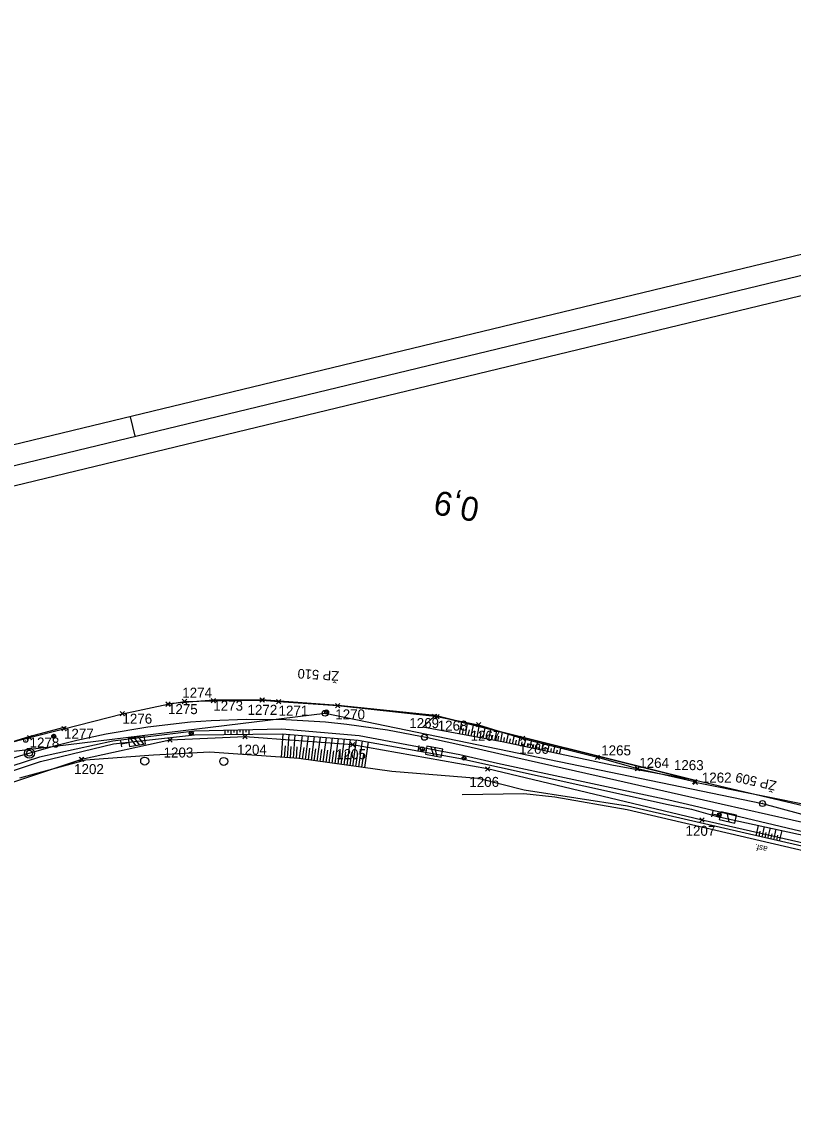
# Model space of a CAD drawing. Extents: x -738085 to -734426, y -1122197 to -1119748.
# Drawn here: x -734969.6 to -734776.9, y -1120258.1 to -1119984.4 of the extents above; entities that cross this region are included whole.
import ezdxf

# ---------------------------------------------------------------- set-up
doc = ezdxf.new("R2010")
doc.units = 0
for name, color, linetype in [('SŽDC', 7, 'Continuous'), ('Vrstva 1', 7, 'Continuous'), ('Vrstva 11', 7, 'Continuous'), ('Vrstva 12', 7, 'Continuous'), ('Vrstva 17', 7, 'Continuous'), ('Vrstva 43', 7, 'Continuous'), ('Vrstva 48', 7, 'Continuous'), ('Vrstva 49', 7, 'Continuous'), ('Vrstva 51', 7, 'Continuous'), ('Vrstva 60', 7, 'Continuous'), ('Vrstva 63', 7, 'Continuous'), ('Vrstva 7', 7, 'Continuous')]:
    doc.layers.add(name, color=color, linetype=linetype)

msp = doc.modelspace()

# ---------------------------------------------------------------- linework, layer by layer
at = {"layer": 'SŽDC'}
for p, q in [((-734933.15, -1120154.76), (-734929.02, -1120154.1)), ((-734929.02, -1120154.1), (-734921.83, -1120153.89)), ((-734921.83, -1120153.89), (-734909.61, -1120153.73)), ((-734909.61, -1120153.73), (-734905.52, -1120154.11)), ((-734905.52, -1120154.11), (-734890.73, -1120155.13)), ((-734944.53, -1120157.15), (-734933.15, -1120154.76)), ((-734890.73, -1120155.13), (-734866.49, -1120157.8)), ((-734959.14, -1120160.9), (-734944.53, -1120157.15)), ((-734866.49, -1120157.8), (-734865.95, -1120157.86)), ((-734865.95, -1120157.86), (-734855.52, -1120159.91)), ((-734967.74, -1120163.1), (-734959.14, -1120160.9)), ((-734855.52, -1120159.91), (-734844.53, -1120163.32)), ((-734977.11, -1120165.51), (-734967.74, -1120163.1)), ((-734932.65, -1120163.73), (-734954.75, -1120168.56)), ((-734913.87, -1120162.91), (-734932.65, -1120163.73)), ((-734887.03, -1120164.91), (-734913.87, -1120162.91)), ((-734853.28, -1120170.95), (-734887.03, -1120164.91)), ((-734844.53, -1120163.32), (-734825.83, -1120168.01)), ((-734954.75, -1120168.56), (-734977.62, -1120176.17)), ((-734825.83, -1120168.01), (-734815.83, -1120170.85)), ((-734799.69, -1120183.7), (-734853.28, -1120170.95)), ((-734815.83, -1120170.85), (-734801.55, -1120174.11)), ((-734801.55, -1120174.11), (-734801.4, -1120174.28)), ((-734801.4, -1120174.28), (-734758.4, -1120182.87)), ((-734748.46, -1120195.41), (-734799.69, -1120183.7))]:
    msp.add_line(p, q, dxfattribs=at)
at = {"layer": 'Vrstva 1'}
msp.add_line((-734941.35, -1120087.84), (-734942.52, -1120082.99), dxfattribs=at)
for points in [[(-734534.27, -1119984.39), (-735554.91, -1120230.88), (-735485.2, -1120519.57), (-734464.55, -1120273.08)], [(-734470.58, -1120269.4), (-735481.51, -1120513.53), (-735548.88, -1120234.56), (-734537.95, -1119990.43)], [(-734541.63, -1119996.45), (-735348.44, -1120191.3), (-735283.42, -1120460.56), (-734476.61, -1120265.71)]]:
    msp.add_lwpolyline(points, close=True, dxfattribs=at)
for points in [[(-734858.48, -1120165.34), (-734868.3, -1120163.18), (-734878.26, -1120161.29), (-734888.48, -1120159.82), (-734893.81, -1120159.28), (-734903.72, -1120158.67), (-734913.62, -1120158.56), (-734922.39, -1120158.89), (-734927.49, -1120159.26), (-734938.14, -1120160.47), (-734948.63, -1120162.22), (-734955.93, -1120163.8), (-734961.26, -1120165.13), (-734970.23, -1120167.73), (-734979.17, -1120170.78), (-734984.57, -1120172.85), (-734992.91, -1120176.44), (-734998.02, -1120178.89), (-735005.2, -1120182.65), (-735013.61, -1120187.35), (-735022.2, -1120192.38), (-735037.65, -1120201.44), (-735048.63, -1120207.9)], [(-734858.48, -1120165.34), (-734868.3, -1120163.18), (-734878.26, -1120161.29), (-734888.48, -1120159.82), (-734893.81, -1120159.28), (-734903.72, -1120158.67), (-734913.62, -1120158.56), (-734922.39, -1120158.89), (-734927.49, -1120159.26), (-734938.14, -1120160.47), (-734948.63, -1120162.22), (-734955.93, -1120163.8), (-734961.26, -1120165.13), (-734970.23, -1120167.73), (-734979.17, -1120170.78), (-734984.57, -1120172.85), (-734992.91, -1120176.44), (-734998.02, -1120178.89), (-735005.2, -1120182.65), (-735013.61, -1120187.35), (-735022.2, -1120192.38), (-735037.65, -1120201.44), (-735048.63, -1120207.9)], [(-734613.42, -1120220.79), (-734634.89, -1120215.96), (-734653.9, -1120211.66), (-734667.21, -1120208.65), (-734679.78, -1120205.8), (-734683.65, -1120204.92), (-734685.4, -1120204.52), (-734700.12, -1120201.2), (-734707.73, -1120199.48), (-734730.99, -1120194.2), (-734759.47, -1120187.75), (-734794.9, -1120179.75), (-734825.42, -1120172.84), (-734846.46, -1120168.09), (-734858.48, -1120165.34)], [(-734613.42, -1120220.79), (-734634.89, -1120215.96), (-734653.9, -1120211.66), (-734667.21, -1120208.65), (-734679.78, -1120205.8), (-734683.65, -1120204.92), (-734685.4, -1120204.52), (-734700.12, -1120201.2), (-734707.73, -1120199.48), (-734730.99, -1120194.2), (-734759.47, -1120187.75), (-734794.9, -1120179.75), (-734825.42, -1120172.84), (-734846.46, -1120168.09), (-734858.48, -1120165.34)]]:
    msp.add_lwpolyline(points, dxfattribs=at)
at = {"layer": 'Vrstva 11'}
for p, q in [((-734893.29, -1120156.29), (-734894, -1120156.87)), ((-734893.06, -1120156.58), (-734893.76, -1120157.16)), ((-734961.61, -1120162.28), (-734962.06, -1120163.09)), ((-734927.17, -1120161.59), (-734927.75, -1120162.31)), ((-734926.88, -1120161.83), (-734927.45, -1120162.54)), ((-734961.29, -1120162.47), (-734961.73, -1120163.27)), ((-734858.86, -1120167.84), (-734859.64, -1120168.33)), ((-734858.66, -1120168.16), (-734859.44, -1120168.64)), ((-734795.13, -1120182.08), (-734795.91, -1120182.57)), ((-734794.93, -1120182.4), (-734795.71, -1120182.89))]:
    msp.add_line(p, q, dxfattribs=at)
for centre in [(-734893.53, -1120156.72), (-734961.68, -1120162.78), (-734927.32, -1120162.06), (-734859.15, -1120168.24), (-734795.43, -1120182.48)]:
    msp.add_circle(centre, 0.5, dxfattribs=at)
at = {"layer": 'Vrstva 12'}
msp.add_lwpolyline([(-734795.73, -1120182), (-734794.95, -1120182.18), (-734795.12, -1120182.96), (-734795.9, -1120182.78), (-734795.73, -1120182)], dxfattribs=at)
at = {"layer": 'Vrstva 17'}
for points in [[(-734749.98, -1120183.69), (-734758.44, -1120182.92), (-734774.19, -1120180.25), (-734801.33, -1120173.81), (-734866.4, -1120157.58), (-734890.66, -1120155.06), (-734909.69, -1120153.67), (-734921.82, -1120153.78), (-734933.01, -1120154.69)], [(-734958.83, -1120160.54), (-734967.92, -1120162.89), (-734987.55, -1120168.9), (-734992.59, -1120171.25), (-735002.18, -1120175.82), (-735016.31, -1120182.77), (-735022.02, -1120185.92), (-735031.95, -1120191.31), (-735046.51, -1120198.52), (-735062.17, -1120206.65)]]:
    msp.add_lwpolyline(points, dxfattribs=at)
at = {"layer": 'Vrstva 43'}
for centre in [(-734938.97, -1120168.99), (-734919.21, -1120169.05)]:
    msp.add_circle(centre, 1, dxfattribs=at)
at = {"layer": 'Vrstva 48'}
for p, q in [((-734860.31, -1120162.2), (-734859.76, -1120159.24)), ((-734858.83, -1120162.47), (-734858.3, -1120159.6)), ((-734918.96, -1120161.37), (-734918.94, -1120162.34)), ((-734918.21, -1120161.35), (-734918.2, -1120161.84)), ((-734917.46, -1120161.33), (-734917.44, -1120162.33)), ((-734916.71, -1120161.31), (-734916.7, -1120161.82)), ((-734915.96, -1120161.3), (-734915.94, -1120162.31)), ((-734915.21, -1120161.28), (-734915.2, -1120161.79)), ((-734914.46, -1120161.26), (-734914.44, -1120162.3)), ((-734913.71, -1120161.25), (-734913.7, -1120161.77)), ((-734912.96, -1120161.23), (-734912.94, -1120162.28)), ((-734904.78, -1120168.03), (-734904.36, -1120162.22)), ((-734903.28, -1120168.14), (-734902.86, -1120162.33)), ((-734859.57, -1120162.34), (-734859.3, -1120160.88)), ((-734858.1, -1120162.61), (-734857.84, -1120161.2)), ((-734857.36, -1120162.75), (-734856.84, -1120159.97)), ((-734856.62, -1120162.88), (-734856.37, -1120161.52)), ((-734855.89, -1120163.02), (-734855.39, -1120160.33)), ((-734855.15, -1120163.16), (-734854.9, -1120161.83)), ((-734854.41, -1120163.29), (-734853.93, -1120160.69)), ((-734853.67, -1120163.43), (-734853.44, -1120162.15)), ((-734852.94, -1120163.57), (-734852.47, -1120161.06)), ((-734851.46, -1120163.84), (-734851.01, -1120161.42)), ((-734849.99, -1120164.11), (-734849.55, -1120161.78)), ((-734848.52, -1120164.41), (-734848.03, -1120162.16)), ((-734901.79, -1120168.25), (-734901.37, -1120162.46)), ((-734900.29, -1120168.37), (-734899.5, -1120162.61)), ((-734898.81, -1120168.57), (-734898, -1120162.73)), ((-734897.32, -1120168.78), (-734896.5, -1120162.85)), ((-734895.83, -1120168.98), (-734895, -1120162.97)), ((-734894.35, -1120169.19), (-734893.51, -1120163.09)), ((-734892.86, -1120169.39), (-734892.01, -1120163.21)), ((-734891.38, -1120169.6), (-734890.51, -1120163.33)), ((-734889.89, -1120169.8), (-734889.01, -1120163.45)), ((-734888.4, -1120170.01), (-734887.52, -1120163.57)), ((-734886.92, -1120170.21), (-734886.02, -1120163.69)), ((-734885.43, -1120170.42), (-734884.54, -1120163.92)), ((-734883.95, -1120170.62), (-734883.06, -1120164.18)), ((-734852.2, -1120163.7), (-734851.97, -1120162.47)), ((-734850.72, -1120163.98), (-734850.5, -1120162.79)), ((-734849.25, -1120164.25), (-734849.04, -1120163.11)), ((-734847.78, -1120164.56), (-734847.54, -1120163.45)), ((-734847.05, -1120164.72), (-734846.58, -1120162.53)), ((-734846.32, -1120164.88), (-734846.08, -1120163.79)), ((-734845.58, -1120165.03), (-734845.12, -1120162.89)), ((-734844.85, -1120165.19), (-734844.62, -1120164.13)), ((-734844.11, -1120165.35), (-734843.67, -1120163.25)), ((-734843.38, -1120165.51), (-734843.16, -1120164.47)), ((-734842.65, -1120165.66), (-734842.21, -1120163.62)), ((-734841.92, -1120165.82), (-734841.7, -1120164.81)), ((-734841.18, -1120165.98), (-734840.75, -1120163.98)), ((-734839.71, -1120166.29), (-734839.3, -1120164.34)), ((-734838.25, -1120166.61), (-734837.84, -1120164.71)), ((-734836.78, -1120166.92), (-734836.39, -1120165.07)), ((-734904.03, -1120168.09), (-734903.82, -1120165.18)), ((-734902.53, -1120168.2), (-734902.33, -1120165.3)), ((-734901.04, -1120168.3), (-734900.83, -1120165.41)), ((-734899.55, -1120168.47), (-734899.15, -1120165.57)), ((-734898.06, -1120168.67), (-734897.66, -1120165.73)), ((-734896.58, -1120168.88), (-734896.17, -1120165.89)), ((-734895.09, -1120169.08), (-734894.67, -1120166.06)), ((-734893.6, -1120169.29), (-734893.18, -1120166.22)), ((-734892.12, -1120169.49), (-734891.69, -1120166.38)), ((-734890.63, -1120169.7), (-734890.2, -1120166.54)), ((-734889.15, -1120169.9), (-734888.71, -1120166.71)), ((-734887.66, -1120170.11), (-734887.21, -1120166.87)), ((-734886.17, -1120170.31), (-734885.72, -1120167.05)), ((-734884.69, -1120170.52), (-734884.24, -1120167.28)), ((-734840.45, -1120166.14), (-734840.24, -1120165.15)), ((-734838.98, -1120166.45), (-734838.78, -1120165.49)), ((-734837.52, -1120166.76), (-734837.31, -1120165.82)), ((-734836.05, -1120167.08), (-734835.85, -1120166.16)), ((-734835.32, -1120167.24), (-734834.93, -1120165.43)), ((-734786.16, -1120187.62), (-734785.56, -1120185.03)), ((-734785.43, -1120187.79), (-734785.13, -1120186.49)), ((-734784.7, -1120187.96), (-734784.09, -1120185.35)), ((-734783.96, -1120188.13), (-734783.66, -1120186.82)), ((-734783.23, -1120188.3), (-734782.63, -1120185.67)), ((-734781.77, -1120188.63), (-734781.16, -1120185.99)), ((-734780.31, -1120188.97), (-734779.7, -1120186.31)), ((-734782.5, -1120188.47), (-734782.2, -1120187.15)), ((-734781.04, -1120188.8), (-734780.74, -1120187.48))]:
    msp.add_line(p, q, dxfattribs=at)
at = {"layer": 'Vrstva 49'}
for p, q in [((-734926.56, -1120161.54), (-734946.95, -1120164.04)), ((-734904.72, -1120161.04), (-734926.56, -1120161.54)), ((-734885.34, -1120162.68), (-734904.72, -1120161.04)), ((-734946.95, -1120164.04), (-734965.26, -1120167.97)), ((-734860.25, -1120167.42), (-734885.34, -1120162.68)), ((-734936.77, -1120167.47), (-734953.78, -1120168.78)), ((-734922.67, -1120166.75), (-734936.77, -1120167.47)), ((-734900.42, -1120168.35), (-734922.67, -1120166.75)), ((-734850.83, -1120169.58), (-734860.25, -1120167.42)), ((-734965.26, -1120167.97), (-734979.99, -1120172.75)), ((-734953.78, -1120168.78), (-734970.28, -1120173.21)), ((-734877.2, -1120171.55), (-734900.42, -1120168.35)), ((-734808.02, -1120178.76), (-734850.83, -1120169.58)), ((-734855.62, -1120173.36), (-734877.2, -1120171.55)), ((-734844.14, -1120176.21), (-734855.62, -1120173.36)), ((-734818.33, -1120180.21), (-734844.14, -1120176.21)), ((-734801.95, -1120180.12), (-734808.02, -1120178.76)), ((-734767.83, -1120191.85), (-734818.33, -1120180.21)), ((-734773.48, -1120186.9), (-734801.95, -1120180.12))]:
    msp.add_line(p, q, dxfattribs=at)
for points in [[(-734869.5, -1120160.5), (-734866.4, -1120157.58), (-734801.33, -1120173.81)], [(-735120.53, -1120253.93), (-735071.24, -1120223.86), (-735031.45, -1120200.68), (-735001.39, -1120183.23), (-734979.37, -1120173.86), (-734964.99, -1120169.04), (-734946.77, -1120164.63), (-734926.51, -1120162.42), (-734904.58, -1120162.2), (-734885.6, -1120163.73), (-734860.45, -1120168.24), (-734808.17, -1120179.8), (-734802.31, -1120181.01), (-734795.9, -1120182.78), (-734795.12, -1120182.96), (-734773.64, -1120187.62), (-734748.07, -1120193.22), (-734734.64, -1120197.94), (-734724.28, -1120200.04), (-734701.99, -1120203.61), (-734701.41, -1120203.78)], [(-734801.33, -1120173.81), (-734822.27, -1120170.03), (-734849.2, -1120164.26), (-734869.5, -1120160.5)]]:
    msp.add_lwpolyline(points, dxfattribs=at)
at = {"layer": 'Vrstva 51'}
msp.add_lwpolyline([(-734722.77, -1120203.71), (-734740.51, -1120199.91), (-734767.99, -1120192.9), (-734818.44, -1120181.19), (-734836.45, -1120178), (-734844.24, -1120177.16), (-734859.66, -1120177.39)], dxfattribs=at)
at = {"layer": 'Vrstva 60'}
for p, q in [((-734928.57, -1120154.55), (-734929.57, -1120153.55)), ((-734928.57, -1120153.65), (-734929.57, -1120154.65)), ((-734929.47, -1120154.55), (-734928.47, -1120153.55)), ((-734929.47, -1120153.65), (-734928.47, -1120154.65)), ((-734929.02, -1120154.1), (-734929.02, -1120154.1)), ((-734921.38, -1120154.34), (-734922.38, -1120153.34)), ((-734921.38, -1120153.44), (-734922.38, -1120154.44)), ((-734922.28, -1120154.34), (-734921.28, -1120153.34)), ((-734922.28, -1120153.44), (-734921.28, -1120154.44)), ((-734921.83, -1120153.89), (-734921.83, -1120153.89)), ((-734909.16, -1120154.18), (-734910.16, -1120153.18)), ((-734909.16, -1120153.28), (-734910.16, -1120154.28)), ((-734910.06, -1120154.18), (-734909.06, -1120153.18)), ((-734910.06, -1120153.28), (-734909.06, -1120154.28)), ((-734909.61, -1120153.73), (-734909.61, -1120153.73)), ((-734905.07, -1120154.56), (-734906.07, -1120153.56)), ((-734905.07, -1120153.66), (-734906.07, -1120154.66)), ((-734905.97, -1120154.56), (-734904.97, -1120153.56)), ((-734905.97, -1120153.66), (-734904.97, -1120154.66)), ((-734905.52, -1120154.11), (-734905.52, -1120154.11)), ((-734944.08, -1120157.6), (-734945.08, -1120156.6)), ((-734944.08, -1120156.7), (-734945.08, -1120157.7)), ((-734944.98, -1120157.6), (-734943.98, -1120156.6)), ((-734944.98, -1120156.7), (-734943.98, -1120157.7)), ((-734932.7, -1120155.21), (-734933.7, -1120154.21)), ((-734932.7, -1120154.31), (-734933.7, -1120155.31)), ((-734933.6, -1120155.21), (-734932.6, -1120154.21)), ((-734933.6, -1120154.31), (-734932.6, -1120155.31)), ((-734933.15, -1120154.76), (-734933.15, -1120154.76)), ((-734890.28, -1120155.58), (-734891.28, -1120154.58)), ((-734890.28, -1120154.68), (-734891.28, -1120155.68)), ((-734891.18, -1120155.58), (-734890.18, -1120154.58)), ((-734891.18, -1120154.68), (-734890.18, -1120155.68)), ((-734890.73, -1120155.13), (-734890.73, -1120155.13)), ((-734944.53, -1120157.15), (-734944.53, -1120157.15)), ((-734866.04, -1120158.25), (-734867.04, -1120157.25)), ((-734866.04, -1120157.35), (-734867.04, -1120158.35)), ((-734866.94, -1120158.25), (-734865.94, -1120157.25)), ((-734866.94, -1120157.35), (-734865.94, -1120158.35)), ((-734865.5, -1120158.31), (-734866.5, -1120157.31)), ((-734865.5, -1120157.41), (-734866.5, -1120158.41)), ((-734866.49, -1120157.8), (-734866.49, -1120157.8)), ((-734866.4, -1120158.31), (-734865.4, -1120157.31)), ((-734866.4, -1120157.41), (-734865.4, -1120158.41)), ((-734865.95, -1120157.86), (-734865.95, -1120157.86)), ((-734855.07, -1120160.36), (-734856.07, -1120159.36)), ((-734855.07, -1120159.46), (-734856.07, -1120160.46)), ((-734855.97, -1120160.36), (-734854.97, -1120159.36)), ((-734855.97, -1120159.46), (-734854.97, -1120160.46)), ((-734958.69, -1120161.35), (-734959.69, -1120160.35)), ((-734958.69, -1120160.45), (-734959.69, -1120161.45)), ((-734959.59, -1120161.35), (-734958.59, -1120160.35)), ((-734959.59, -1120160.45), (-734958.59, -1120161.45)), ((-734959.14, -1120160.9), (-734959.14, -1120160.9)), ((-734913.42, -1120163.36), (-734914.42, -1120162.36)), ((-734914.32, -1120163.36), (-734913.32, -1120162.36)), ((-734855.52, -1120159.91), (-734855.52, -1120159.91)), ((-734967.29, -1120163.55), (-734968.29, -1120162.55)), ((-734967.29, -1120162.65), (-734968.29, -1120163.65)), ((-734968.19, -1120163.55), (-734967.19, -1120162.55)), ((-734968.19, -1120162.65), (-734967.19, -1120163.65)), ((-734967.74, -1120163.1), (-734967.74, -1120163.1)), ((-734932.2, -1120164.18), (-734933.2, -1120163.18)), ((-734932.2, -1120163.28), (-734933.2, -1120164.28)), ((-734933.1, -1120164.18), (-734932.1, -1120163.18)), ((-734933.1, -1120163.28), (-734932.1, -1120164.28)), ((-734932.65, -1120163.73), (-734932.65, -1120163.73)), ((-734913.42, -1120162.46), (-734914.42, -1120163.46)), ((-734914.32, -1120162.46), (-734913.32, -1120163.46)), ((-734913.87, -1120162.91), (-734913.87, -1120162.91)), ((-734886.58, -1120165.36), (-734887.58, -1120164.36)), ((-734886.58, -1120164.46), (-734887.58, -1120165.46)), ((-734887.48, -1120165.36), (-734886.48, -1120164.36)), ((-734887.48, -1120164.46), (-734886.48, -1120165.46)), ((-734887.03, -1120164.91), (-734887.03, -1120164.91)), ((-734844.08, -1120163.77), (-734845.08, -1120162.77)), ((-734844.08, -1120162.87), (-734845.08, -1120163.87)), ((-734844.98, -1120163.77), (-734843.98, -1120162.77)), ((-734844.98, -1120162.87), (-734843.98, -1120163.87)), ((-734844.53, -1120163.32), (-734844.53, -1120163.32)), ((-734825.38, -1120168.46), (-734826.38, -1120167.46)), ((-734825.38, -1120167.56), (-734826.38, -1120168.56)), ((-734826.28, -1120168.46), (-734825.28, -1120167.46)), ((-734826.28, -1120167.56), (-734825.28, -1120168.56)), ((-734954.3, -1120169.01), (-734955.3, -1120168.01)), ((-734954.3, -1120168.11), (-734955.3, -1120169.11)), ((-734955.2, -1120169.01), (-734954.2, -1120168.01)), ((-734955.2, -1120168.11), (-734954.2, -1120169.11)), ((-734954.75, -1120168.56), (-734954.75, -1120168.56)), ((-734852.83, -1120171.4), (-734853.83, -1120170.4)), ((-734852.83, -1120170.5), (-734853.83, -1120171.5)), ((-734853.73, -1120171.4), (-734852.73, -1120170.4)), ((-734853.73, -1120170.5), (-734852.73, -1120171.5)), ((-734825.83, -1120168.01), (-734825.83, -1120168.01)), ((-734815.38, -1120171.3), (-734816.38, -1120170.3)), ((-734815.38, -1120170.4), (-734816.38, -1120171.4)), ((-734816.28, -1120171.3), (-734815.28, -1120170.3)), ((-734816.28, -1120170.4), (-734815.28, -1120171.4)), ((-734853.28, -1120170.95), (-734853.28, -1120170.95)), ((-734815.83, -1120170.85), (-734815.83, -1120170.85)), ((-734801.1, -1120174.56), (-734802.1, -1120173.56)), ((-734801.1, -1120173.66), (-734802.1, -1120174.66)), ((-734802, -1120174.56), (-734801, -1120173.56)), ((-734802, -1120173.66), (-734801, -1120174.66)), ((-734800.95, -1120174.73), (-734801.95, -1120173.73)), ((-734800.95, -1120173.83), (-734801.95, -1120174.83)), ((-734801.85, -1120174.73), (-734800.85, -1120173.73)), ((-734801.85, -1120173.83), (-734800.85, -1120174.83)), ((-734801.55, -1120174.11), (-734801.55, -1120174.11)), ((-734801.4, -1120174.28), (-734801.4, -1120174.28)), ((-734799.24, -1120184.15), (-734800.24, -1120183.15)), ((-734799.24, -1120183.25), (-734800.24, -1120184.25)), ((-734800.14, -1120184.15), (-734799.14, -1120183.15)), ((-734800.14, -1120183.25), (-734799.14, -1120184.25)), ((-734799.69, -1120183.7), (-734799.69, -1120183.7))]:
    msp.add_line(p, q, dxfattribs=at)
at = {"layer": 'Vrstva 63'}
for p, q in [((-734977.95, -1120167.28), (-734893.88, -1120157.02)), ((-734893.83, -1120157.03), (-734893.93, -1120157.02)), ((-734893.88, -1120157.02), (-734784.59, -1120179.58)), ((-734784.54, -1120179.59), (-734784.64, -1120179.57)), ((-734784.59, -1120179.58), (-734667.47, -1120210.99))]:
    msp.add_line(p, q, dxfattribs=at)
for centre in [(-734893.88, -1120157.02), (-734784.59, -1120179.58)]:
    msp.add_circle(centre, 0.756, dxfattribs=at)
at = {"layer": 'Vrstva 7'}
for p, q in [((-734968.65, -1120163.77), (-734968.74, -1120163.8)), ((-734944.99, -1120163.95), (-734944.74, -1120165.43)), ((-734942.57, -1120163.29), (-734941.25, -1120165.1)), ((-734940.26, -1120164.93), (-734941.58, -1120163.12)), ((-734940.59, -1120162.96), (-734939.28, -1120164.77)), ((-734870.44, -1120165.12), (-734870.72, -1120166.6)), ((-734869.56, -1120165.95), (-734869.65, -1120165.93)), ((-734867.45, -1120165.44), (-734866.84, -1120167.59)), ((-734865.86, -1120167.78), (-734866.47, -1120165.63)), ((-734796.98, -1120181.41), (-734797.31, -1120182.87)), ((-734793.51, -1120181.94), (-734792.98, -1120184.11))]:
    msp.add_line(p, q, dxfattribs=at)
for points in [[(-734944.87, -1120164.69), (-734942.9, -1120164.36), (-734942.73, -1120165.34), (-734938.79, -1120164.68), (-734939.12, -1120162.71), (-734943.06, -1120163.37), (-734942.9, -1120164.36)], [(-734870.58, -1120165.86), (-734868.62, -1120166.24), (-734868.8, -1120167.22), (-734864.87, -1120167.97), (-734864.5, -1120166), (-734868.43, -1120165.25), (-734868.62, -1120166.24)], [(-734797.15, -1120182.14), (-734795.2, -1120182.58), (-734795.42, -1120183.56), (-734791.52, -1120184.44), (-734791.08, -1120182.49), (-734794.98, -1120181.61), (-734795.2, -1120182.58)]]:
    msp.add_lwpolyline(points, dxfattribs=at)
for centre, radius in [((-734869.05, -1120163.04), 0.75), ((-734869.05, -1120163.04), 0.75), ((-734968.7, -1120163.78), 0.5), ((-734967.76, -1120167.01), 1.25), ((-734967.76, -1120167.01), 0.752), ((-734869.6, -1120165.94), 0.5)]:
    msp.add_circle(centre, radius, dxfattribs=at)

# ---------------------------------------------------------------- texts
at = {"layer": 'Vrstva 51'}
msp.add_text('asf.', height=1.5, rotation=166.938, dxfattribs=at).set_placement((-734783.23, -1120190.36))
at = {"layer": 'Vrstva 60'}
for s, p in [('1274', (-734929.58, -1120153.15)), ('1273', (-734921.83, -1120156.39)), ('1275', (-734933.15, -1120157.26)), ('1272', (-734913.28, -1120157.43)), ('1271', (-734905.52, -1120157.64)), ('1270', (-734891.35, -1120158.57)), ('1276', (-734944.53, -1120159.65)), ('1269', (-734872.85, -1120160.74)), ('1268', (-734865.75, -1120161.37)), ('1277', (-734959.14, -1120163.4)), ('1267', (-734857.53, -1120163.91)), ('1278', (-734967.74, -1120165.6)), ('1204', (-734915.88, -1120167.37)), ('1266', (-734845.41, -1120167.16)), ('1265', (-734824.89, -1120167.56)), ('1203', (-734934.25, -1120168.09)), ('1205', (-734891.12, -1120168.5)), ('1202', (-734956.61, -1120172.23)), ('1264', (-734815.39, -1120170.67)), ('1263', (-734806.73, -1120171.24)), ('1206', (-734857.85, -1120175.43)), ('1262', (-734799.75, -1120174.35)), ('1207', (-734803.82, -1120187.64))]:
    msp.add_text(s, height=2.5, dxfattribs=at).set_placement(p)
at = {"layer": 'Vrstva 63'}
for s, rotation, p in [('ŽP 510', 176.46, (-734890.34, -1120146.56)), ('ŽP 509', 167.2679, (-734780.91, -1120174.06))]:
    msp.add_text(s, height=2.4, rotation=rotation, dxfattribs=at).set_placement(p)
at = {"layer": 'Vrstva 7'}
msp.add_text('0,9', height=6, rotation=169.221, dxfattribs=at).set_placement((-734854.99, -1120103.43))
msp.add_text('0,9', height=6, rotation=169.221, dxfattribs=at).set_placement((-734854.99, -1120103.43))

doc.saveas('drawing.dxf')
